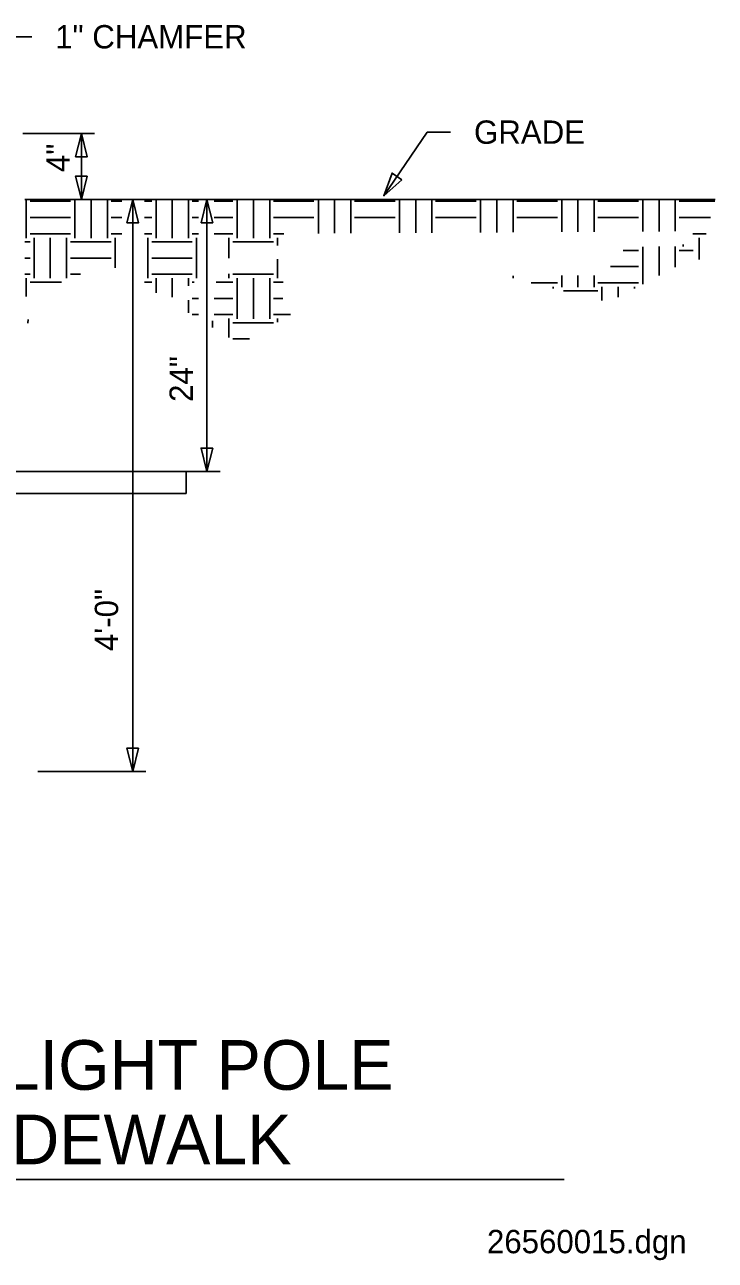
# Model space of a CAD drawing. Extents: x 10122.8 to 10170.2, y 10095.7 to 10157.1.
# Drawn here: x 10150.52 to 10170.24, y 10095.67 to 10130.92 of the extents above; entities that cross this region are included whole.
import ezdxf

# ---------------------------------------------------------------- set-up
doc = ezdxf.new("R2010")
doc.units = 0
for name, color, linetype in [('G-ANNO-TEXT', 7, 'Continuous'), ('G-DETL-LINE', 7, 'Continuous'), ('G-DETL-OTLN', 7, 'Continuous'), ('G-DETL-PATT', 7, 'Continuous')]:
    doc.layers.add(name, color=color, linetype=linetype)

msp = doc.modelspace()

# ---------------------------------------------------------------- linework, layer by layer
at = {"layer": 'G-ANNO-TEXT'}
for p, q in [((10150.719, 10130.582), (10150.053, 10130.582)), ((10150.463, 10127.825), (10152.511, 10127.825)), ((10152.136, 10127.825), (10152.136, 10125.939)), ((10162.012, 10127.859), (10160.767, 10126.045)), ((10162.679, 10127.859), (10162.012, 10127.859)), ((10153.601, 10125.939), (10153.601, 10109.619)), ((10155.719, 10118.177), (10155.719, 10125.939)), ((10154.045, 10118.177), (10156.094, 10118.177)), ((10150.891, 10109.619), (10153.976, 10109.619)), ((10127.401, 10097.976), (10165.925, 10097.976))]:
    msp.add_line(p, q, dxfattribs=at)
for points in [[(10151.969, 10127.159), (10152.136, 10127.825), (10152.303, 10127.159)], [(10152.303, 10126.606), (10152.136, 10125.939), (10151.969, 10126.606)], [(10161.282, 10126.5), (10160.767, 10126.045), (10161.007, 10126.689)], [(10153.434, 10125.272), (10153.601, 10125.939), (10153.767, 10125.272)], [(10155.552, 10125.272), (10155.719, 10125.939), (10155.886, 10125.272)], [(10155.886, 10118.844), (10155.719, 10118.177), (10155.552, 10118.844)], [(10153.767, 10110.286), (10153.601, 10109.619), (10153.434, 10110.286)]]:
    msp.add_lwpolyline(points, close=True, dxfattribs=at)
at = {"layer": 'G-DETL-LINE'}
msp.add_line((10170.236, 10125.939), (10150.516, 10125.939), dxfattribs=at)
at = {"layer": 'G-DETL-OTLN'}
for p, q in [((10149.313, 10118.177), (10155.122, 10118.177)), ((10155.122, 10118.177), (10155.122, 10117.552)), ((10155.122, 10117.552), (10149.313, 10117.552))]:
    msp.add_line(p, q, dxfattribs=at)
at = {"layer": 'G-DETL-PATT'}
for p, q in [((10150.562, 10125.939), (10150.562, 10124.838)), ((10150.669, 10125.889), (10151.827, 10125.889)), ((10151.951, 10125.939), (10151.951, 10124.838)), ((10152.415, 10125.939), (10152.415, 10124.838)), ((10152.878, 10125.939), (10152.878, 10124.838)), ((10152.985, 10125.889), (10153.289, 10125.889)), ((10153.937, 10125.889), (10154.143, 10125.889)), ((10154.268, 10125.939), (10154.268, 10124.838)), ((10154.731, 10125.939), (10154.731, 10124.838)), ((10155.194, 10125.939), (10155.194, 10124.838)), ((10155.302, 10125.889), (10155.477, 10125.889)), ((10155.928, 10125.889), (10156.46, 10125.889)), ((10156.584, 10125.939), (10156.584, 10124.838)), ((10157.048, 10125.939), (10157.048, 10124.838)), ((10157.511, 10125.939), (10157.511, 10124.838)), ((10157.618, 10125.889), (10158.776, 10125.889)), ((10158.901, 10125.939), (10158.901, 10124.97)), ((10159.364, 10125.939), (10159.364, 10124.973)), ((10159.827, 10125.939), (10159.827, 10124.975)), ((10159.934, 10125.889), (10161.093, 10125.889)), ((10161.217, 10125.939), (10161.217, 10124.984)), ((10161.68, 10125.939), (10161.68, 10124.986)), ((10162.144, 10125.939), (10162.144, 10124.989)), ((10162.251, 10125.889), (10163.409, 10125.889)), ((10163.533, 10125.939), (10163.533, 10124.997)), ((10163.997, 10125.939), (10163.997, 10125)), ((10164.46, 10125.939), (10164.46, 10125.003)), ((10164.567, 10125.889), (10165.726, 10125.889)), ((10165.85, 10125.939), (10165.85, 10125.011)), ((10166.313, 10125.939), (10166.313, 10125.014)), ((10166.776, 10125.939), (10166.776, 10125.017)), ((10166.884, 10125.889), (10168.042, 10125.889)), ((10168.166, 10125.939), (10168.166, 10125.025)), ((10168.63, 10125.939), (10168.63, 10125.027)), ((10169.093, 10125.939), (10169.093, 10125.03)), ((10169.2, 10125.889), (10170.222, 10125.889)), ((10150.669, 10125.425), (10151.827, 10125.425)), ((10152.985, 10125.425), (10153.289, 10125.425)), ((10153.937, 10125.425), (10154.143, 10125.425)), ((10155.302, 10125.425), (10155.477, 10125.425)), ((10155.928, 10125.425), (10156.46, 10125.425)), ((10157.618, 10125.425), (10158.776, 10125.425)), ((10159.934, 10125.425), (10161.093, 10125.425)), ((10162.251, 10125.425), (10163.409, 10125.425)), ((10164.567, 10125.425), (10165.726, 10125.425)), ((10166.884, 10125.425), (10168.042, 10125.425)), ((10169.2, 10125.425), (10170.099, 10125.425)), ((10150.516, 10124.73), (10150.669, 10124.73)), ((10150.669, 10124.962), (10151.827, 10124.962)), ((10150.785, 10124.846), (10150.785, 10123.688)), ((10151.248, 10124.846), (10151.248, 10123.688)), ((10151.711, 10124.846), (10151.711, 10123.688)), ((10151.827, 10124.73), (10152.985, 10124.73)), ((10152.985, 10124.962), (10153.289, 10124.962)), ((10153.101, 10124.846), (10153.101, 10123.992)), ((10153.937, 10124.962), (10154.143, 10124.962)), ((10154.028, 10124.846), (10154.028, 10123.688)), ((10154.143, 10124.73), (10155.302, 10124.73)), ((10155.302, 10124.962), (10155.477, 10124.962)), ((10155.417, 10124.846), (10155.417, 10123.688)), ((10155.928, 10124.962), (10156.46, 10124.962)), ((10156.344, 10124.846), (10156.344, 10124.26)), ((10156.46, 10124.73), (10157.618, 10124.73)), ((10157.618, 10124.962), (10157.92, 10124.962)), ((10157.734, 10124.846), (10157.734, 10124.622)), ((10169.593, 10124.962), (10169.976, 10124.962)), ((10169.779, 10124.846), (10169.779, 10124.223)), ((10167.607, 10124.486), (10168.042, 10124.486)), ((10168.166, 10124.588), (10168.166, 10123.521)), ((10168.63, 10124.594), (10168.63, 10123.764)), ((10169.093, 10124.594), (10169.093, 10124.007)), ((10169.2, 10124.486), (10169.608, 10124.486)), ((10169.316, 10124.649), (10169.316, 10124.594)), ((10150.516, 10124.267), (10150.669, 10124.267)), ((10151.827, 10124.267), (10152.985, 10124.267)), ((10154.143, 10124.267), (10155.302, 10124.267)), ((10157.734, 10124.231), (10157.734, 10123.688)), ((10167.244, 10124.023), (10168.042, 10124.023)), ((10150.516, 10123.804), (10150.669, 10123.804)), ((10150.562, 10123.688), (10150.562, 10123.169)), ((10151.827, 10123.804), (10152.108, 10123.804)), ((10154.143, 10123.804), (10155.302, 10123.804)), ((10154.268, 10123.688), (10154.268, 10123.275)), ((10154.731, 10123.688), (10154.731, 10123.154)), ((10155.194, 10123.688), (10155.194, 10123.472)), ((10156.344, 10123.82), (10156.344, 10123.688)), ((10156.46, 10123.804), (10157.618, 10123.804)), ((10156.584, 10123.688), (10156.584, 10122.53)), ((10157.048, 10123.688), (10157.048, 10122.53)), ((10157.511, 10123.688), (10157.511, 10122.53)), ((10164.46, 10123.759), (10164.46, 10123.689)), ((10165.85, 10123.764), (10165.85, 10123.436)), ((10166.313, 10123.766), (10166.313, 10123.436)), ((10166.776, 10123.767), (10166.776, 10123.436)), ((10150.669, 10123.58), (10151.563, 10123.58)), ((10153.937, 10123.58), (10154.143, 10123.58)), ((10155.302, 10123.58), (10155.352, 10123.58)), ((10155.981, 10123.58), (10156.46, 10123.58)), ((10157.618, 10123.58), (10157.897, 10123.58)), ((10164.976, 10123.56), (10165.726, 10123.56)), ((10165.61, 10123.444), (10165.61, 10123.401)), ((10165.902, 10123.328), (10166.884, 10123.328)), ((10166.884, 10123.56), (10168.042, 10123.56)), ((10167, 10123.444), (10167, 10123.054)), ((10167.463, 10123.444), (10167.463, 10123.153)), ((10167.926, 10123.444), (10167.926, 10123.395)), ((10155.194, 10123.062), (10155.194, 10122.706)), ((10155.302, 10123.117), (10155.477, 10123.117)), ((10155.928, 10123.117), (10156.46, 10123.117)), ((10157.618, 10123.117), (10157.89, 10123.117)), ((10155.302, 10122.654), (10155.477, 10122.654)), ((10155.928, 10122.654), (10156.46, 10122.654)), ((10156.344, 10122.538), (10156.344, 10122)), ((10157.618, 10122.654), (10158.107, 10122.654)), ((10157.734, 10122.538), (10157.734, 10122.433)), ((10150.602, 10122.409), (10150.619, 10122.517)), ((10155.881, 10122.474), (10155.881, 10122.284)), ((10156.46, 10122.422), (10157.618, 10122.422)), ((10156.46, 10121.959), (10156.933, 10121.959))]:
    msp.add_line(p, q, dxfattribs=at)

# ---------------------------------------------------------------- texts
at = {"layer": 'G-ANNO-TEXT'}
for s, height, p in [('1" CHAMFER', 0.6667, (10151.386, 10130.248)), ('GRADE', 0.6667, (10163.346, 10127.526)), ('TYPICAL PEDESTRIAN LIGHT POLE', 1.41667, (10128.836, 10100.533)), ('BASE TOUCHING SIDEWALK', 1.41667, (10132.136, 10098.408)), ('26560015.dgn', 0.66667, (10163.715, 10095.869))]:
    msp.add_text(s, height=height, dxfattribs=at).set_placement(p)
for s, p in [('4"', (10151.797, 10126.719)), ('24"', (10155.318, 10120.161)), ('4\'-0"', (10153.184, 10113.05))]:
    msp.add_text(s, height=0.6667, rotation=90, dxfattribs=at).set_placement(p)

doc.saveas('drawing.dxf')
